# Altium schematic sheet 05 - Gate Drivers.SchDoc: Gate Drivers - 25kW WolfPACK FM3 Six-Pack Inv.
size 431 x 279 mm; Date: 09/2024; DocumentNumber: CRD25DA12N-FMC; Revision: 2.0; SheetNumber: 5; SheetTotal: 9; SheetSize: B
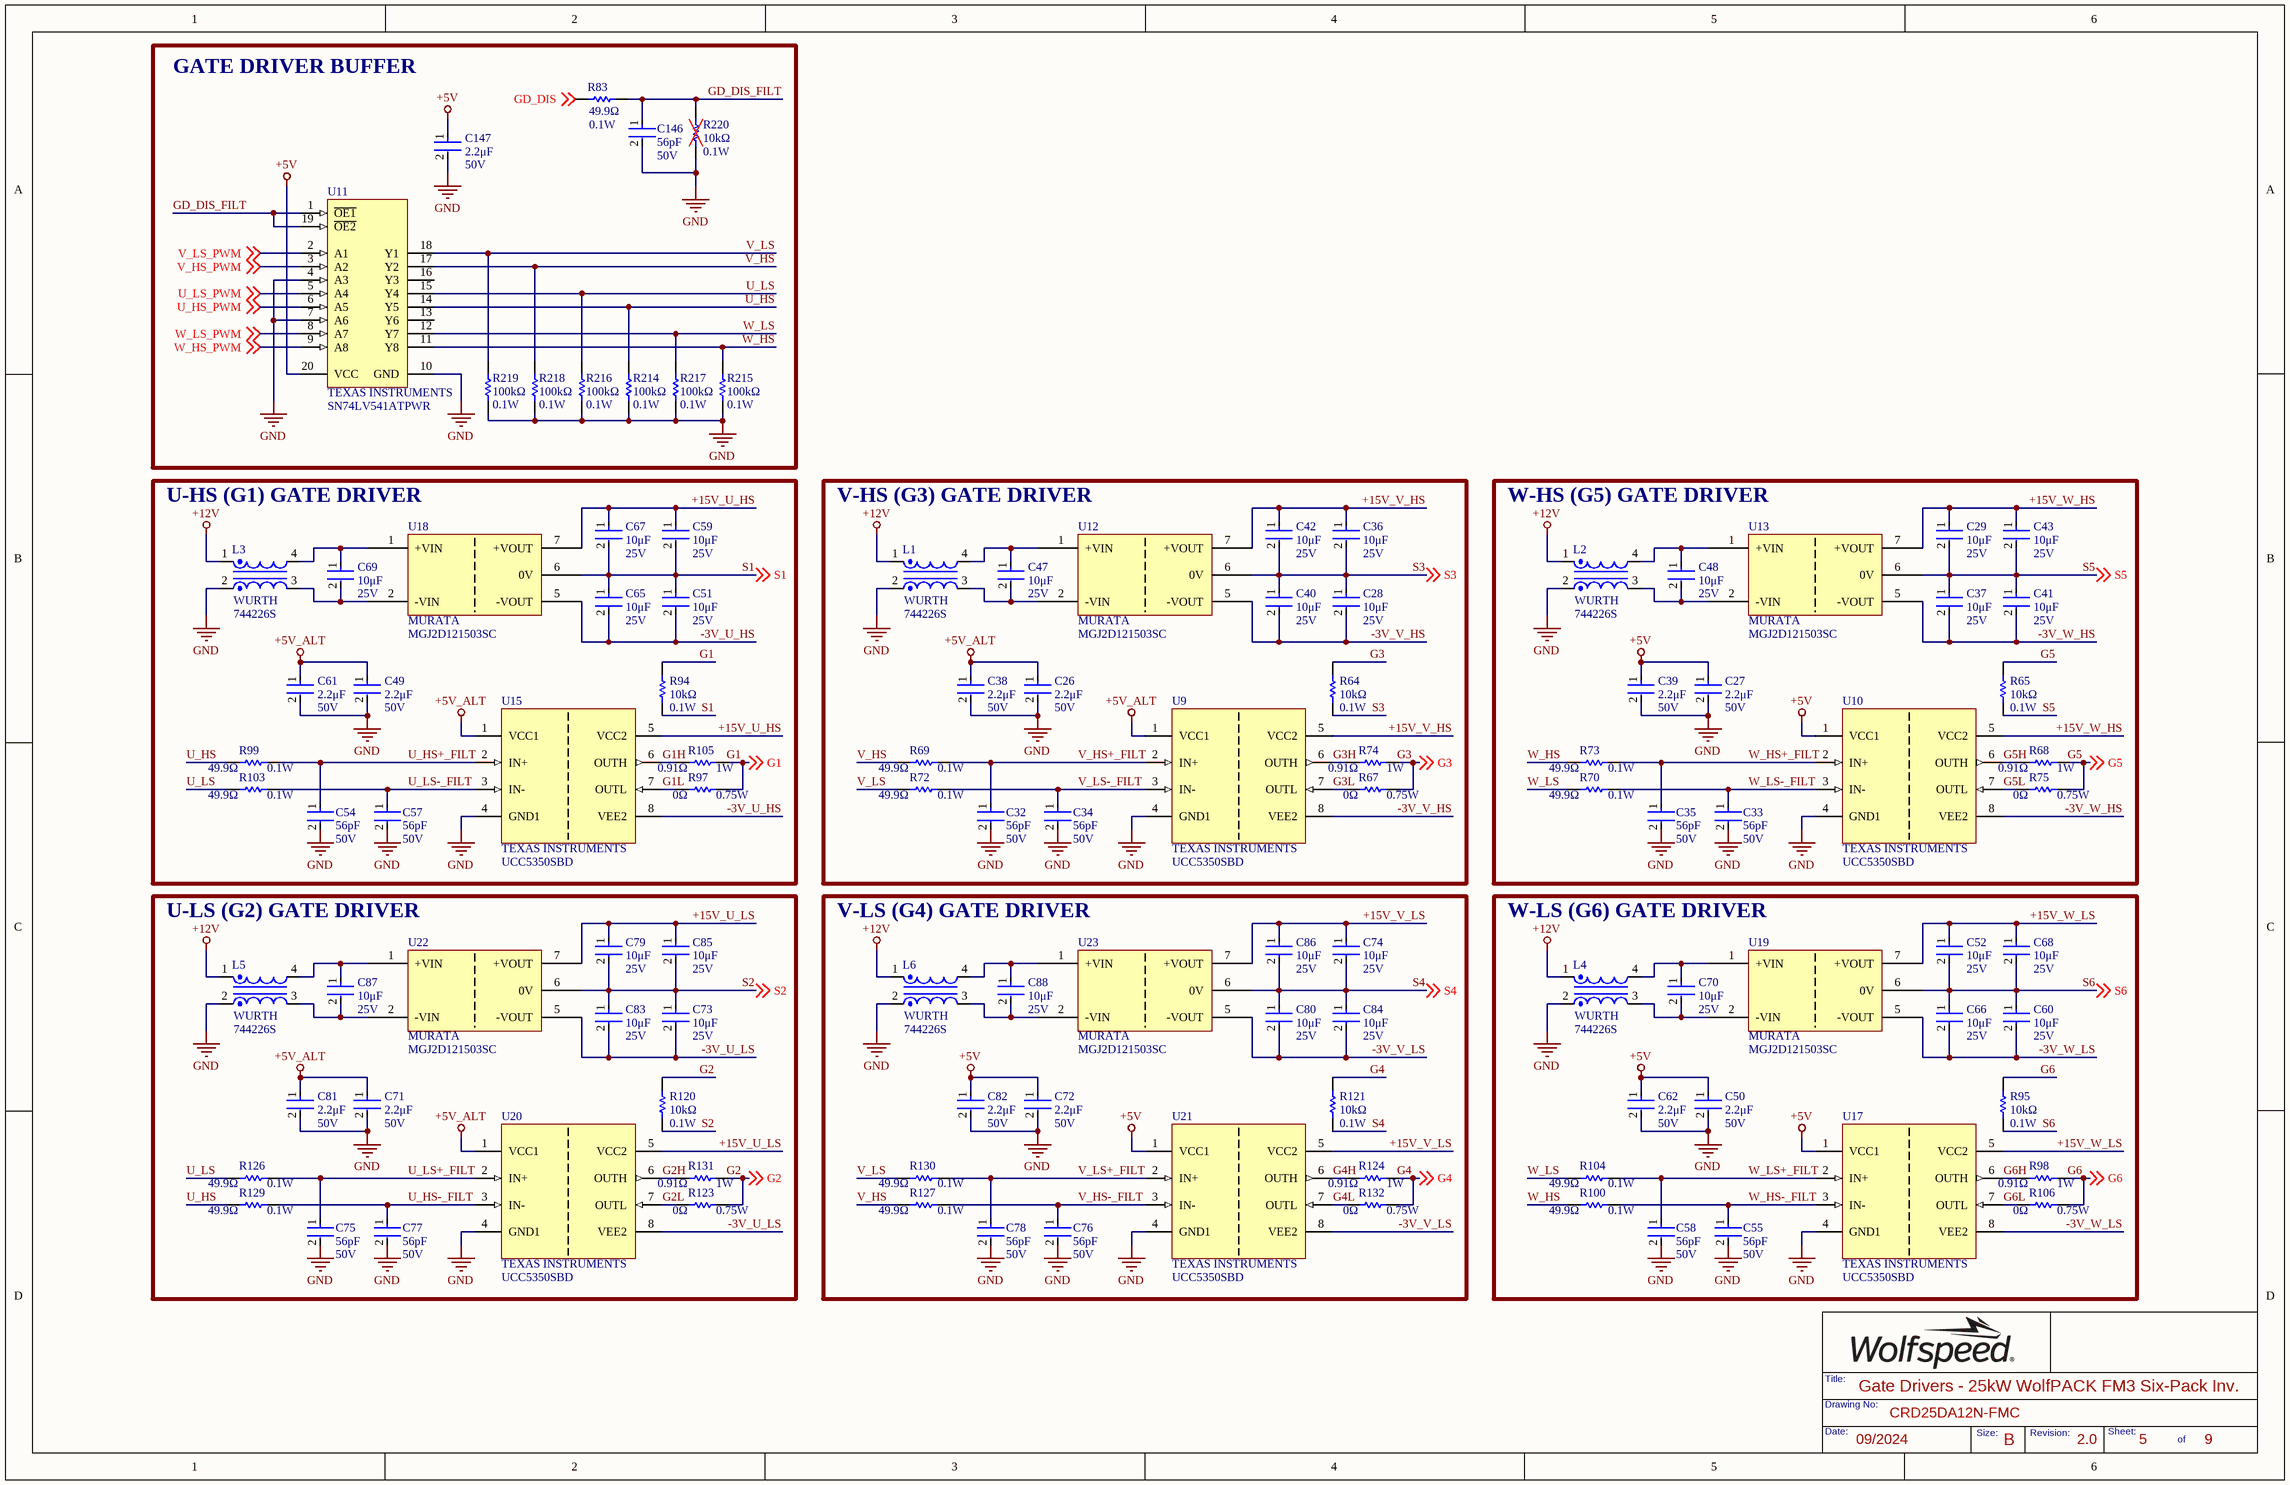
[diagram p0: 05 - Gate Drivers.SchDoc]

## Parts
C26  Voltage Rating: 50V  Capacitance: 2.2μF  [FP-C0603C-CF-IPC_B]  (hidden comment: GRT188R61H225ME13D)
C27  Voltage Rating: 50V  Capacitance: 2.2μF  [FP-C0603C-CF-IPC_B]  (hidden comment: GRT188R61H225ME13D)
C28  Voltage Rating: 25V  Capacitance: 10μF  [FP-CL31-IPC_B]  (hidden comment: CL31B106KAHSFNE)
C29  Voltage Rating: 25V  Capacitance: 10μF  [FP-CL31-IPC_B]  (hidden comment: CL31B106KAHSFNE)
C32  Capacitance: 56pF  Voltage Rating: 50V  [FP-C0603C-CF-IPC_B]  (hidden comment: CL10C560JB8NNNC)
C33  Capacitance: 56pF  Voltage Rating: 50V  [FP-C0603C-CF-IPC_B]  (hidden comment: CL10C560JB8NNNC)
C34  Capacitance: 56pF  Voltage Rating: 50V  [FP-C0603C-CF-IPC_B]  (hidden comment: CL10C560JB8NNNC)
C35  Capacitance: 56pF  Voltage Rating: 50V  [FP-C0603C-CF-IPC_B]  (hidden comment: CL10C560JB8NNNC)
C36  Voltage Rating: 25V  Capacitance: 10μF  [FP-CL31-IPC_B]  (hidden comment: CL31B106KAHSFNE)
C37  Voltage Rating: 25V  Capacitance: 10μF  [FP-CL31-IPC_B]  (hidden comment: CL31B106KAHSFNE)
C38  Voltage Rating: 50V  Capacitance: 2.2μF  [FP-C0603C-CF-IPC_B]  (hidden comment: GRT188R61H225ME13D)
C39  Voltage Rating: 50V  Capacitance: 2.2μF  [FP-C0603C-CF-IPC_B]  (hidden comment: GRT188R61H225ME13D)
C40  Voltage Rating: 25V  Capacitance: 10μF  [FP-CL31-IPC_B]  (hidden comment: CL31B106KAHSFNE)
C41  Voltage Rating: 25V  Capacitance: 10μF  [FP-CL31-IPC_B]  (hidden comment: CL31B106KAHSFNE)
C42  Voltage Rating: 25V  Capacitance: 10μF  [FP-CL31-IPC_B]  (hidden comment: CL31B106KAHSFNE)
C43  Voltage Rating: 25V  Capacitance: 10μF  [FP-CL31-IPC_B]  (hidden comment: CL31B106KAHSFNE)
C47  Voltage Rating: 25V  Capacitance: 10μF  [FP-CL31-IPC_B]  (hidden comment: CL31B106KAHSFNE)
C48  Voltage Rating: 25V  Capacitance: 10μF  [FP-CL31-IPC_B]  (hidden comment: CL31B106KAHSFNE)
C49  Voltage Rating: 50V  Capacitance: 2.2μF  [FP-C0603C-CF-IPC_B]  (hidden comment: GRT188R61H225ME13D)
C50  Voltage Rating: 50V  Capacitance: 2.2μF  [FP-C0603C-CF-IPC_B]  (hidden comment: GRT188R61H225ME13D)
C51  Voltage Rating: 25V  Capacitance: 10μF  [FP-CL31-IPC_B]  (hidden comment: CL31B106KAHSFNE)
C52  Voltage Rating: 25V  Capacitance: 10μF  [FP-CL31-IPC_B]  (hidden comment: CL31B106KAHSFNE)
C54  Capacitance: 56pF  Voltage Rating: 50V  [FP-C0603C-CF-IPC_B]  (hidden comment: CL10C560JB8NNNC)
C55  Capacitance: 56pF  Voltage Rating: 50V  [FP-C0603C-CF-IPC_B]  (hidden comment: CL10C560JB8NNNC)
C57  Capacitance: 56pF  Voltage Rating: 50V  [FP-C0603C-CF-IPC_B]  (hidden comment: CL10C560JB8NNNC)
C58  Capacitance: 56pF  Voltage Rating: 50V  [FP-C0603C-CF-IPC_B]  (hidden comment: CL10C560JB8NNNC)
C59  Voltage Rating: 25V  Capacitance: 10μF  [FP-CL31-IPC_B]  (hidden comment: CL31B106KAHSFNE)
C60  Voltage Rating: 25V  Capacitance: 10μF  [FP-CL31-IPC_B]  (hidden comment: CL31B106KAHSFNE)
C61  Voltage Rating: 50V  Capacitance: 2.2μF  [FP-C0603C-CF-IPC_B]  (hidden comment: GRT188R61H225ME13D)
C62  Voltage Rating: 50V  Capacitance: 2.2μF  [FP-C0603C-CF-IPC_B]  (hidden comment: GRT188R61H225ME13D)
C65  Voltage Rating: 25V  Capacitance: 10μF  [FP-CL31-IPC_B]  (hidden comment: CL31B106KAHSFNE)
C66  Voltage Rating: 25V  Capacitance: 10μF  [FP-CL31-IPC_B]  (hidden comment: CL31B106KAHSFNE)
C67  Voltage Rating: 25V  Capacitance: 10μF  [FP-CL31-IPC_B]  (hidden comment: CL31B106KAHSFNE)
C68  Voltage Rating: 25V  Capacitance: 10μF  [FP-CL31-IPC_B]  (hidden comment: CL31B106KAHSFNE)
C69  Voltage Rating: 25V  Capacitance: 10μF  [FP-CL31-IPC_B]  (hidden comment: CL31B106KAHSFNE)
C70  Voltage Rating: 25V  Capacitance: 10μF  [FP-CL31-IPC_B]  (hidden comment: CL31B106KAHSFNE)
C71  Voltage Rating: 50V  Capacitance: 2.2μF  [FP-C0603C-CF-IPC_B]  (hidden comment: GRT188R61H225ME13D)
C72  Voltage Rating: 50V  Capacitance: 2.2μF  [FP-C0603C-CF-IPC_B]  (hidden comment: GRT188R61H225ME13D)
C73  Voltage Rating: 25V  Capacitance: 10μF  [FP-CL31-IPC_B]  (hidden comment: CL31B106KAHSFNE)
C74  Voltage Rating: 25V  Capacitance: 10μF  [FP-CL31-IPC_B]  (hidden comment: CL31B106KAHSFNE)
C75  Capacitance: 56pF  Voltage Rating: 50V  [FP-C0603C-CF-IPC_B]  (hidden comment: CL10C560JB8NNNC)
C76  Capacitance: 56pF  Voltage Rating: 50V  [FP-C0603C-CF-IPC_B]  (hidden comment: CL10C560JB8NNNC)
C77  Capacitance: 56pF  Voltage Rating: 50V  [FP-C0603C-CF-IPC_B]  (hidden comment: CL10C560JB8NNNC)
C78  Capacitance: 56pF  Voltage Rating: 50V  [FP-C0603C-CF-IPC_B]  (hidden comment: CL10C560JB8NNNC)
C79  Voltage Rating: 25V  Capacitance: 10μF  [FP-CL31-IPC_B]  (hidden comment: CL31B106KAHSFNE)
C80  Voltage Rating: 25V  Capacitance: 10μF  [FP-CL31-IPC_B]  (hidden comment: CL31B106KAHSFNE)
C81  Voltage Rating: 50V  Capacitance: 2.2μF  [FP-C0603C-CF-IPC_B]  (hidden comment: GRT188R61H225ME13D)
C82  Voltage Rating: 50V  Capacitance: 2.2μF  [FP-C0603C-CF-IPC_B]  (hidden comment: GRT188R61H225ME13D)
C83  Voltage Rating: 25V  Capacitance: 10μF  [FP-CL31-IPC_B]  (hidden comment: CL31B106KAHSFNE)
C84  Voltage Rating: 25V  Capacitance: 10μF  [FP-CL31-IPC_B]  (hidden comment: CL31B106KAHSFNE)
C85  Voltage Rating: 25V  Capacitance: 10μF  [FP-CL31-IPC_B]  (hidden comment: CL31B106KAHSFNE)
C86  Voltage Rating: 25V  Capacitance: 10μF  [FP-CL31-IPC_B]  (hidden comment: CL31B106KAHSFNE)
C87  Voltage Rating: 25V  Capacitance: 10μF  [FP-CL31-IPC_B]  (hidden comment: CL31B106KAHSFNE)
C88  Voltage Rating: 25V  Capacitance: 10μF  [FP-CL31-IPC_B]  (hidden comment: CL31B106KAHSFNE)
C146  Capacitance: 56pF  Voltage Rating: 50V  [FP-C0603C-CF-IPC_B]  (hidden comment: CL10C560JB8NNNC)
C147  Voltage Rating: 50V  Capacitance: 2.2μF  [FP-C0603C-CF-IPC_B]  (hidden comment: GRT188R61H225ME13D)
L1  744226S  Manufacturer Print: WURTH  [WE-SL2]
L2  744226S  Manufacturer Print: WURTH  [WE-SL2]
L3  744226S  Manufacturer Print: WURTH  [WE-SL2]
L4  744226S  Manufacturer Print: WURTH  [WE-SL2]
L5  744226S  Manufacturer Print: WURTH  [WE-SL2]
L6  744226S  Manufacturer Print: WURTH  [WE-SL2]
R64  Resistance: 10kΩ  Max Power Dissipation: 0.1W  [FP-MCR03-IPC_B]  (hidden comment: ERJ3EKF1002V)
R65  Resistance: 10kΩ  Max Power Dissipation: 0.1W  [FP-MCR03-IPC_B]  (hidden comment: ERJ3EKF1002V)
R67  value 0Ω  Power Rating: 0.75W  [RESC3125X70X40NL20T20]  (hidden comment: CRCW12100000Z0EAHP)
R68  value 0.91Ω  Power: 1W  [RESC3125X70X40NL20T20]  (hidden comment: RCWE1210R910FKEA)
R69  Resistance: 49.9Ω  Power Rating: 0.1W  [FP-MCR03-IPC_B]  (hidden comment: ERJ-3EKF49R9V)
R70  Resistance: 49.9Ω  Power Rating: 0.1W  [FP-MCR03-IPC_B]  (hidden comment: ERJ-3EKF49R9V)
R72  Resistance: 49.9Ω  Power Rating: 0.1W  [FP-MCR03-IPC_B]  (hidden comment: ERJ-3EKF49R9V)
R73  Resistance: 49.9Ω  Power Rating: 0.1W  [FP-MCR03-IPC_B]  (hidden comment: ERJ-3EKF49R9V)
R74  value 0.91Ω  Power: 1W  [RESC3125X70X40NL20T20]  (hidden comment: RCWE1210R910FKEA)
R75  value 0Ω  Power Rating: 0.75W  [RESC3125X70X40NL20T20]  (hidden comment: CRCW12100000Z0EAHP)
R83  Resistance: 49.9Ω  Power Rating: 0.1W  [FP-MCR03-IPC_B]  (hidden comment: ERJ-3EKF49R9V)
R94  Resistance: 10kΩ  Max Power Dissipation: 0.1W  [FP-MCR03-IPC_B]  (hidden comment: ERJ3EKF1002V)
R95  Resistance: 10kΩ  Max Power Dissipation: 0.1W  [FP-MCR03-IPC_B]  (hidden comment: ERJ3EKF1002V)
R97  value 0Ω  Power Rating: 0.75W  [RESC3125X70X40NL20T20]  (hidden comment: CRCW12100000Z0EAHP)
R98  value 0.91Ω  Power: 1W  [RESC3125X70X40NL20T20]  (hidden comment: RCWE1210R910FKEA)
R99  Resistance: 49.9Ω  Power Rating: 0.1W  [FP-MCR03-IPC_B]  (hidden comment: ERJ-3EKF49R9V)
R100  Resistance: 49.9Ω  Power Rating: 0.1W  [FP-MCR03-IPC_B]  (hidden comment: ERJ-3EKF49R9V)
R103  Resistance: 49.9Ω  Power Rating: 0.1W  [FP-MCR03-IPC_B]  (hidden comment: ERJ-3EKF49R9V)
R104  Resistance: 49.9Ω  Power Rating: 0.1W  [FP-MCR03-IPC_B]  (hidden comment: ERJ-3EKF49R9V)
R105  value 0.91Ω  Power: 1W  [RESC3125X70X40NL20T20]  (hidden comment: RCWE1210R910FKEA)
R106  value 0Ω  Power Rating: 0.75W  [RESC3125X70X40NL20T20]  (hidden comment: CRCW12100000Z0EAHP)
R120  Resistance: 10kΩ  Max Power Dissipation: 0.1W  [FP-MCR03-IPC_B]  (hidden comment: ERJ3EKF1002V)
R121  Resistance: 10kΩ  Max Power Dissipation: 0.1W  [FP-MCR03-IPC_B]  (hidden comment: ERJ3EKF1002V)
R123  value 0Ω  Power Rating: 0.75W  [RESC3125X70X40NL20T20]  (hidden comment: CRCW12100000Z0EAHP)
R124  value 0.91Ω  Power: 1W  [RESC3125X70X40NL20T20]  (hidden comment: RCWE1210R910FKEA)
R126  Resistance: 49.9Ω  Power Rating: 0.1W  [FP-MCR03-IPC_B]  (hidden comment: ERJ-3EKF49R9V)
R127  Resistance: 49.9Ω  Power Rating: 0.1W  [FP-MCR03-IPC_B]  (hidden comment: ERJ-3EKF49R9V)
R129  Resistance: 49.9Ω  Power Rating: 0.1W  [FP-MCR03-IPC_B]  (hidden comment: ERJ-3EKF49R9V)
R130  Resistance: 49.9Ω  Power Rating: 0.1W  [FP-MCR03-IPC_B]  (hidden comment: ERJ-3EKF49R9V)
R131  value 0.91Ω  Power: 1W  [RESC3125X70X40NL20T20]  (hidden comment: RCWE1210R910FKEA)
R132  value 0Ω  Power Rating: 0.75W  [RESC3125X70X40NL20T20]  (hidden comment: CRCW12100000Z0EAHP)
R214  Resistance: 100kΩ  Power Rating: 0.1W  [FP-MCR03-IPC_B]  (hidden comment: RC0603FR-07100KL)
R215  Resistance: 100kΩ  Power Rating: 0.1W  [FP-MCR03-IPC_B]  (hidden comment: RC0603FR-07100KL)
R216  Resistance: 100kΩ  Power Rating: 0.1W  [FP-MCR03-IPC_B]  (hidden comment: RC0603FR-07100KL)
R217  Resistance: 100kΩ  Power Rating: 0.1W  [FP-MCR03-IPC_B]  (hidden comment: RC0603FR-07100KL)
R218  Resistance: 100kΩ  Power Rating: 0.1W  [FP-MCR03-IPC_B]  (hidden comment: RC0603FR-07100KL)
R219  Resistance: 100kΩ  Power Rating: 0.1W  [FP-MCR03-IPC_B]  (hidden comment: RC0603FR-07100KL)
R220  Resistance: 10kΩ  Max Power Dissipation: 0.1W  [FP-MCR03-IPC_B]  (hidden comment: ERJ3EKF1002V)
U9  UCC5350SBD  Manufacturer Print: TEXAS INSTRUMENTS  [D0008B_HV]
U10  UCC5350SBD  Manufacturer Print: TEXAS INSTRUMENTS  [D0008B_HV]
U11  Manufacturer: TEXAS INSTRUMENTS  [PW0020A_L]  (hidden comment: SN74LV541ATPWR)
U12  MGJ2D121503SC  Manufacturer Print: MURATA  [MGJ2D121509SC]
U13  MGJ2D121503SC  Manufacturer Print: MURATA  [MGJ2D121509SC]
U15  UCC5350SBD  Manufacturer Print: TEXAS INSTRUMENTS  [D0008B_HV]
U17  UCC5350SBD  Manufacturer Print: TEXAS INSTRUMENTS  [D0008B_HV]
U18  MGJ2D121503SC  Manufacturer Print: MURATA  [MGJ2D121509SC]
U19  MGJ2D121503SC  Manufacturer Print: MURATA  [MGJ2D121509SC]
U20  UCC5350SBD  Manufacturer Print: TEXAS INSTRUMENTS  [D0008B_HV]
U21  UCC5350SBD  Manufacturer Print: TEXAS INSTRUMENTS  [D0008B_HV]
U22  MGJ2D121503SC  Manufacturer Print: MURATA  [MGJ2D121509SC]
U23  MGJ2D121503SC  Manufacturer Print: MURATA  [MGJ2D121509SC]

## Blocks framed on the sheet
GATE DRIVER BUFFER: C146 C147 R83 R214-R220 U11
U-HS (G1) GATE DRIVER: C49 C51 C54 C57 C59 C61 C65 C67 C69 L3 R94 R97 R99 R103 R105 U15 U18
V-HS (G3) GATE DRIVER: C26 C28 C32 C34 C36 C38 C40 C42 C47 L1 R64 R67 R69 R72 R74 U9 U12
W-HS (G5) GATE DRIVER: C27 C29 C33 C35 C37 C39 C41 C43 C48 L2 R65 R68 R70 R73 R75 U10 U13
U-LS (G2) GATE DRIVER: C71 C73 C75 C77 C79 C81 C83 C85 C87 L5 R120 R123 R126 R129 R131 U20 U22
V-LS (G4) GATE DRIVER: C72 C74 C76 C78 C80 C82 C84 C86 C88 L6 R121 R124 R127 R130 R132 U21 U23
W-LS (G6) GATE DRIVER: C50 C52 C55 C58 C60 C62 C66 C68 C70 L4 R95 R98 R100 R104 R106 U17 U19

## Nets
+5V: C27.1 C39.1 C50.1 C62.1 C72.1 C82.1 C147.1 U10.1(VCC1) U11.20(VCC) U17.1(VCC1) U21.1(VCC1)
+5V_ALT: C26.1 C38.1 C49.1 C61.1 C71.1 C81.1 U9.1(VCC1) U15.1(VCC1) U20.1(VCC1)
+12V: L1.1 L2.1 L3.1 L4.1 L5.1 L6.1
GND: C26.2 C27.2 C32.2 C33.2 C34.2 C35.2 C38.2 C39.2 C49.2 C50.2 C54.2 C55.2 C57.2 C58.2 C61.2 C62.2 C71.2 C72.2 C75.2 C76.2 C77.2 C78.2 C81.2 C82.2 C146.2 C147.2 L1.2 L2.2 L3.2 L4.2 L5.2 L6.2 R214.1 R215.1 R216.1 R217.1 R218.1 R219.1 R220.1 U9.4(GND1) U10.4(GND1) U11.4(A3) U11.7(A6) U11.10(GND) U15.4(GND1) U17.4(GND1) U20.4(GND1) U21.4(GND1)
+15V_U_HS: C59.1 C67.1 U15.5(VCC2) U18.7(+VOUT)
+15V_U_LS: C79.1 C85.1 U20.5(VCC2) U22.7(+VOUT)
+15V_V_HS: C36.1 C42.1 U9.5(VCC2) U12.7(+VOUT)
+15V_V_LS: C74.1 C86.1 U21.5(VCC2) U23.7(+VOUT)
+15V_W_HS: C29.1 C43.1 U10.5(VCC2) U13.7(+VOUT)
+15V_W_LS: C52.1 C68.1 U17.5(VCC2) U19.7(+VOUT)
-3V_U_HS: C51.2 C65.2 U15.8(VEE2) U18.5(-VOUT)
-3V_U_LS: C73.2 C83.2 U20.8(VEE2) U22.5(-VOUT)
-3V_V_HS: C28.2 C40.2 U9.8(VEE2) U12.5(-VOUT)
-3V_V_LS: C80.2 C84.2 U21.8(VEE2) U23.5(-VOUT)
-3V_W_HS: C37.2 C41.2 U10.8(VEE2) U13.5(-VOUT)
-3V_W_LS: C60.2 C66.2 U17.8(VEE2) U19.5(-VOUT)
G1: R94.2 R97.2 R105.2 ; off-sheet G1
G1H: R105.1 U15.6(OUTH)
G1L: R97.1 U15.7(OUTL)
G2: R120.2 R123.2 R131.2 ; off-sheet G2
G2H: R131.1 U20.6(OUTH)
G2L: R123.1 U20.7(OUTL)
G3: R64.2 R67.2 R74.2 ; off-sheet G3
G3H: R74.1 U9.6(OUTH)
G3L: R67.1 U9.7(OUTL)
G4: R121.2 R124.2 R132.2 ; off-sheet G4
G4H: R124.1 U21.6(OUTH)
G4L: R132.1 U21.7(OUTL)
G5: R65.2 R68.2 R75.2 ; off-sheet G5
G5H: R68.1 U10.6(OUTH)
G5L: R75.1 U10.7(OUTL)
G6: R95.2 R98.2 R106.2 ; off-sheet G6
G6H: R98.1 U17.6(OUTH)
G6L: R106.1 U17.7(OUTL)
GD_DIS: R83.1 ; off-sheet GD_DIS
GD_DIS_FILT: C146.1 R83.2 R220.2 U11.1(~{OE1}) U11.19(~{OE2})
S1: C51.1 C59.2 C65.1 C67.2 R94.1 U18.6(0V) ; off-sheet S1
S2: C73.1 C79.2 C83.1 C85.2 R120.1 U22.6(0V) ; off-sheet S2
S3: C28.1 C36.2 C40.1 C42.2 R64.1 U12.6(0V) ; off-sheet S3
S4: C74.2 C80.1 C84.1 C86.2 R121.1 U23.6(0V) ; off-sheet S4
S5: C29.2 C37.1 C41.1 C43.2 R65.1 U13.6(0V) ; off-sheet S5
S6: C52.2 C60.1 C66.1 C68.2 R95.1 U19.6(0V) ; off-sheet S6
U_HS: R99.1 R129.1 R214.2 U11.14(Y5)
U_HS+_FILT: C54.1 R99.2 U15.2(IN+)
U_HS-_FILT: C77.1 R129.2 U20.3(IN-)
U_HS_PWM: U11.6(A5) ; off-sheet U_HS_PWM
U_LS: R103.1 R126.1 R216.2 U11.15(Y4)
U_LS+_FILT: C75.1 R126.2 U20.2(IN+)
U_LS-_FILT: C57.1 R103.2 U15.3(IN-)
U_LS_PWM: U11.5(A4) ; off-sheet U_LS_PWM
V_HS: R69.1 R127.1 R218.2 U11.17(Y2)
V_HS+_FILT: C32.1 R69.2 U9.2(IN+)
V_HS-_FILT: C76.1 R127.2 U21.3(IN-)
V_HS_PWM: U11.3(A2) ; off-sheet V_HS_PWM
V_LS: R72.1 R130.1 R219.2 U11.18(Y1)
V_LS+_FILT: C78.1 R130.2 U21.2(IN+)
V_LS-_FILT: C34.1 R72.2 U9.3(IN-)
V_LS_PWM: U11.2(A1) ; off-sheet V_LS_PWM
W_HS: R73.1 R100.1 R215.2 U11.11(Y8)
W_HS+_FILT: C35.1 R73.2 U10.2(IN+)
W_HS-_FILT: C55.1 R100.2 U17.3(IN-)
W_HS_PWM: U11.9(A8) ; off-sheet W_HS_PWM
W_LS: R70.1 R104.1 R217.2 U11.12(Y7)
W_LS+_FILT: C58.1 R104.2 U17.2(IN+)
W_LS-_FILT: C33.1 R70.2 U10.3(IN-)
W_LS_PWM: U11.8(A7) ; off-sheet W_LS_PWM
NetC47_1: C47.1 L1.4 U12.1(+VIN)
NetC47_2: C47.2 L1.3 U12.2(-VIN)
NetC48_1: C48.1 L2.4 U13.1(+VIN)
NetC48_2: C48.2 L2.3 U13.2(-VIN)
NetC69_1: C69.1 L3.4 U18.1(+VIN)
NetC69_2: C69.2 L3.3 U18.2(-VIN)
NetC70_1: C70.1 L4.4 U19.1(+VIN)
NetC70_2: C70.2 L4.3 U19.2(-VIN)
NetC87_1: C87.1 L5.4 U22.1(+VIN)
NetC87_2: C87.2 L5.3 U22.2(-VIN)
NetC88_1: C88.1 L6.4 U23.1(+VIN)
NetC88_2: C88.2 L6.3 U23.2(-VIN)

Not connected (* = marked no-connect by the designer): U11 13(Y6) 16(Y3)

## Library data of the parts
C26 C27 C38 C39 C49 C50 C61 C62 C71 C72 C81 C82 C147 = GRT188R61H225ME13D: CAP CER 2.2UF 50V X5R 0603; Manufacturer: MURATA; Tolerance: 20%; Value: 2.2μF
C28 C29 C36 C37 C40-C43 C47 C48 C51 C52 C59 C60 C65-C70 C73 C74 C79 C80 C83-C88 = CMP-13271-001434-1: CAP CER 10UF 25V X7R 1206; Manufacturer: SAMSUNG; Tolerance: 10%; Value: 10μF
C32-C35 C54 C55 C57 C58 C75-C78 C146 = CL10C560JB8NNNC: CAP CER 56PF 50V C0G/NP0 0603; Manufacturer: SAMSUNG; Material: Ceramic; Tolerance: 5%; Dielectric: C0G; Temperature Coefficient: 30ppm/°C
L1-L6 = 744226S: CMC 10UH 1.6A 2LN 920 OHM SMD; Manufacturer: WURTH ELECTRONIK; Tolerance: 30%; Voltage Rating: 80V; Resistance: 80mR; Impedance: 920R; Number of Lines: 2; Test Frequency: 1kHz; Value: 10μH
R64 R65 R94 R95 R120 R121 R220 = ERJ3EKF1002V: RES SMD 10K OHM 1% 1/10W 0603; Manufacturer: PANASONIC; Manufacturer Part Number: ERJ-3EKF1002V; Temperature Coefficient: 100ppm/°C; Power Rating: 100mW; Voltage Rating: 75V; Value: 10kΩ
R67 R75 R97 R106 R123 R132 = CRCW12100000Z0EAHP: RES SMD 0 OHM JUMPER 3/4W 1210; Manufacturer: VISHAY DALE; Max Power Dissipation: 750mW
R68 R74 R98 R105 R124 R131 = CMP-2005-02198-1: RES 0.91 OHM 1% 1W 1210; Manufacturer: VISHAY DALE
R69 R70 R72 R73 R83 R99 R100 R103 R104 R126 R127 R129 R130 = ERJ-3EKF49R9V: RES SMD 49.9 OHM 1% 1/10W 0603; Manufacturer: PANASONIC; Temperature Coefficient: 100ppm/°C; Voltage Rating: 75V; Max Power Dissipation: 100mW; Voltage Rating (DC): 50V; Working Voltage: 6V; Value: 49.9Ω
R214-R219 = RC0603FR-07100KL: RES 100K OHM 1% 1/10W 0603; Manufacturer: YAGEO; Temperature Coefficient: 100ppm/°C; Voltage Rating: 50V; Working Voltage: 75V; Max Power Dissipation: 100mW; Value: 100kΩ
U9 U10 U15 U17 U20 U21 = UCC5350SBD: 5A/5A, 3-KVRMS SINGLE-CHANNEL IS; Class: U; Working Voltage: 990V; Number of Channels: 1
U11 = CMP-0440-01163-3: IC BUF NON-INVERT 5.5V 20TSSOP; Bits(#): 8; Voltage(Nom)(V): 5; ICC @ Nom Voltage(Max)(mA): 0.02; VCC(Max)(V): 5.5; Output Type: CMOS; Rating: Catalog; Input Type: TTL; VCC(Min)(V): 4.5; F @ Nom Voltage(Max)(Mhz): 110; tpd @ Nom Voltage(Max)(ns): 7.9
U12 U13 U18 U19 U22 U23 = MGJ2D121503SC: DC DC CONVERTER 15V -3V 1.7W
